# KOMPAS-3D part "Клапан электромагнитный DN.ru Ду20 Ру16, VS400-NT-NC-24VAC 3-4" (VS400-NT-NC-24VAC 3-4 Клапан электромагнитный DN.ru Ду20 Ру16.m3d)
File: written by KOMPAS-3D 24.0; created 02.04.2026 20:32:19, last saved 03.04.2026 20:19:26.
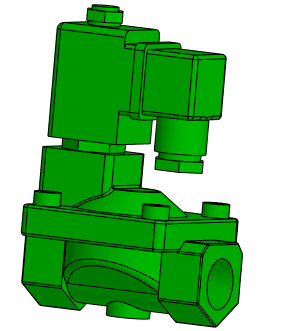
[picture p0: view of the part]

Document properties: Автор: artio; Полное имя файла: C:\Users\artio\OneDrive\Рабочий стол\Клапан электромагнитный DN.ru\VS400-NT-NC\VS400-NT-NC-24VAC 3-4 Клапан электромагнитный DN.ru Ду20 Ру16.m3d

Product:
- Body: Тело 1  | qty 1
    Масса: 1.210539
- Part/product: Клапан электромагнитный DN.ru Ду20 Ру16  | designation VS400-NT-NC-24VAC 3-4
    Масса: 0.954
    Раздел спецификации: Прочие изделия
    Примечание: D130-05493
    additional columns: ef56311e-7521-43dc-8291-0e6108b3d81d; VS400-ET-NC-220VAC 3-4; artio; c; Шероховатость не задана; Да

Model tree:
1. Операция без истории:1

Expressions: VS400-NT-NC-24VAC 3-4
